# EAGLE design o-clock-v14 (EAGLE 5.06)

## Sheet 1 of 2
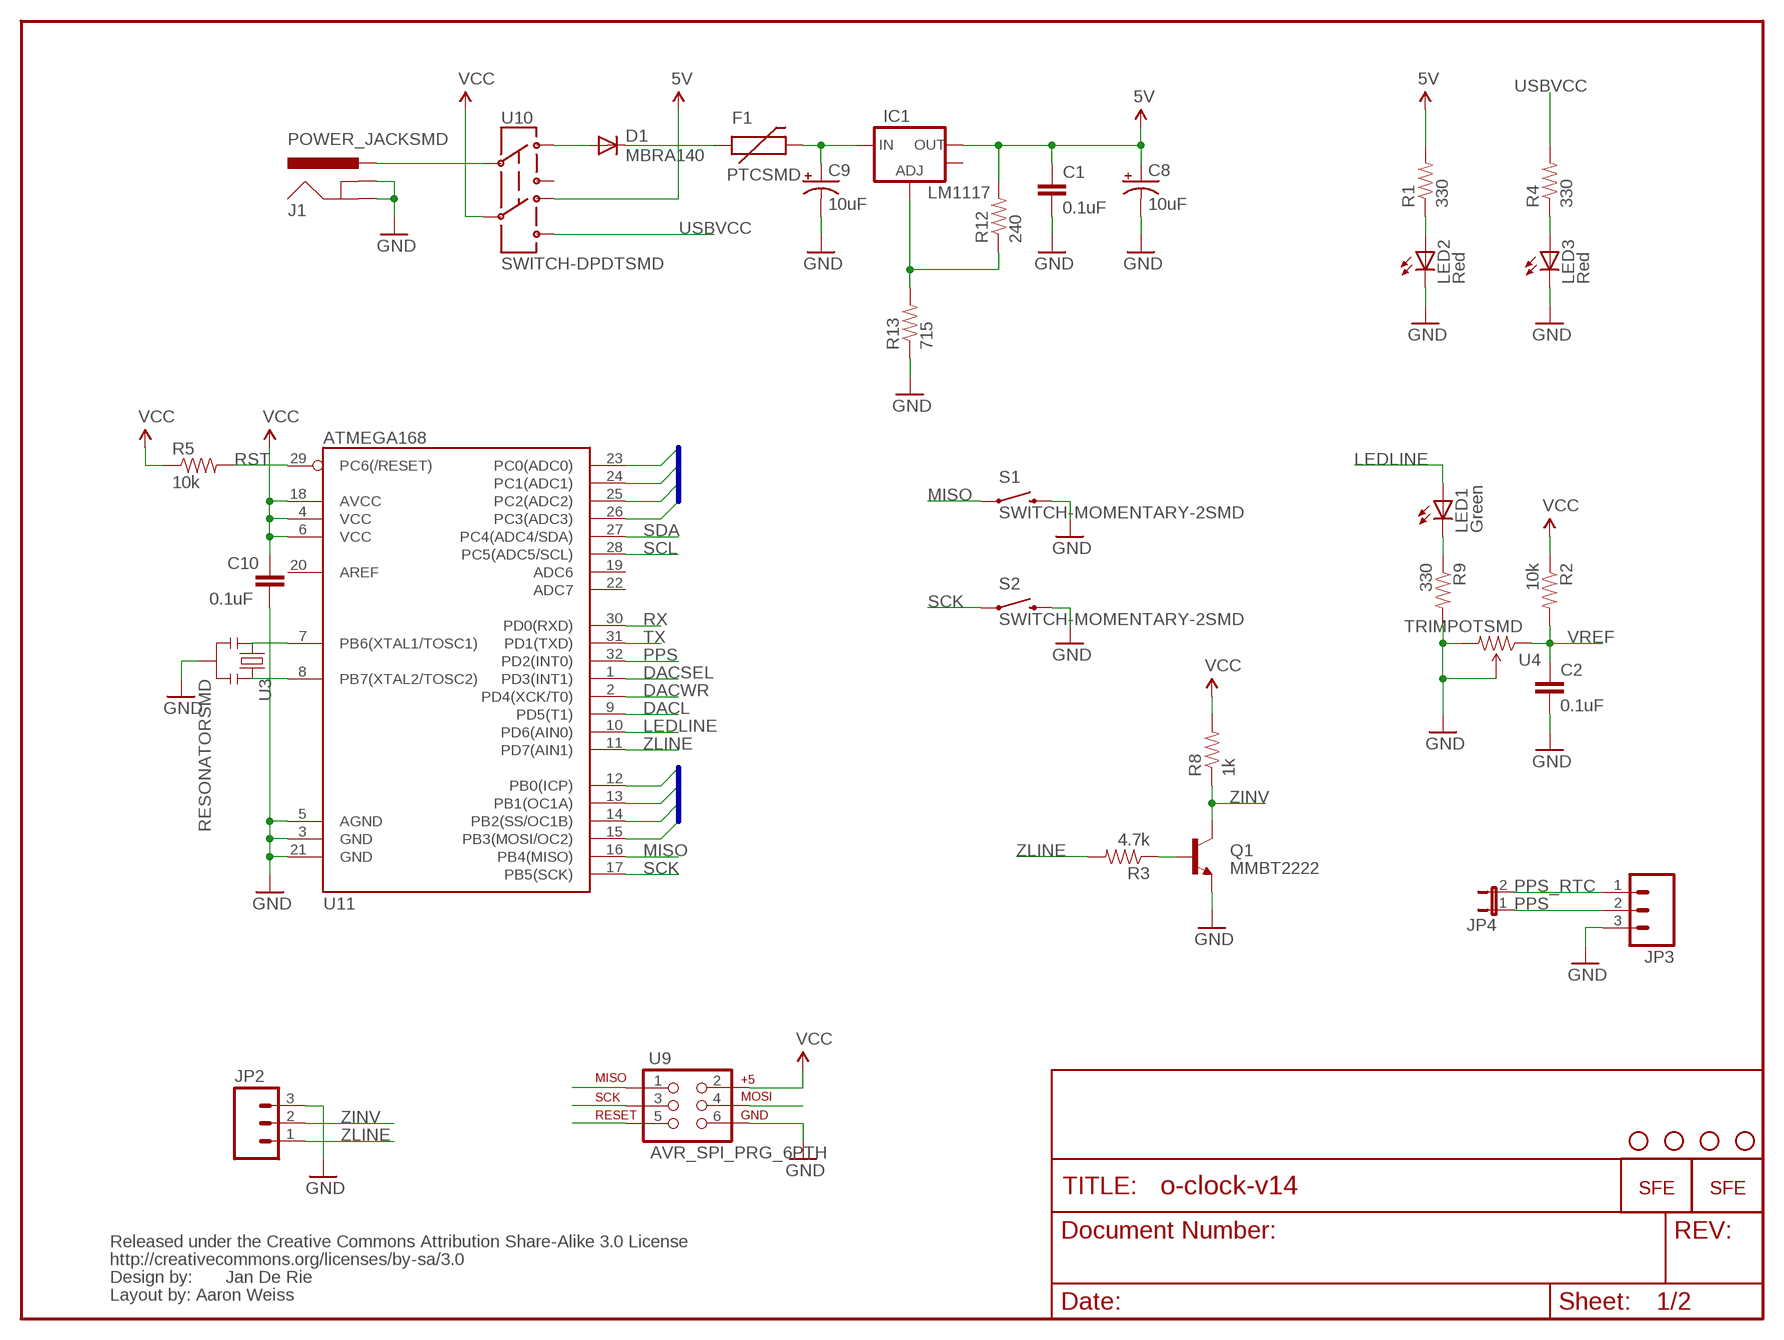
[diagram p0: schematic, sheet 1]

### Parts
C1  0.1uF  CAP0402-CAP  [0402-CAP]
C2  0.1uF  CAP0402-CAP  [0402-CAP]
C8  10uF  CAP_POL1206  [EIA3216]
C9  10uF  CAP_POL1206  [EIA3216]
C10  0.1uF  CAP0402-CAP  [0402-CAP]
D1  MBRA140  DIODESMA  [SMA-DIODE]
F1  PTCSMD  [PTC-1206]
IC1  LM1117  V_REG_LM1117SOT223  [SOT223]
J1  POWER_JACKSMD  [POWER_JACK_SMD]
JP2  M03PTH  [1X03]
JP3  M03PTH  [1X03]
JP4  JUMPER-2SMD-NC  [SJ_2S]
LED1  Green  LED0603  [LED-0603]
LED2  Red  LED0603  [LED-0603]
LED3  Red  LED0603  [LED-0603]
Q1  MMBT2222  TRANSISTOR_NPNSOT23-3  [SOT23-3]
R1  330  RESISTOR0402-RES  [0402-RES]
R2  10k  RESISTOR0402-RES  [0402-RES]
R3  4.7k  RESISTOR0402-RES  [0402-RES]
R4  330  RESISTOR0402-RES  [0402-RES]
R5  10k  RESISTOR0402-RES  [0402-RES]
R8  1k  RESISTOR0402-RES  [0402-RES]
R9  330  RESISTOR0402-RES  [0402-RES]
R12  240  RESISTOR0402-RES  [0402-RES]
R13  715  RESISTOR0402-RES  [0402-RES]
S1  SWITCH-MOMENTARY-2SMD  [TACTILE_SWITCH_SMD]
S2  SWITCH-MOMENTARY-2SMD  [TACTILE_SWITCH_SMD]
U3  RESONATORSMD  [RESONATOR-SMD]
U4  TRIMPOTSMD  [TRIMPOT-3MM]
U9  AVR_SPI_PRG_6PTH  [2X3]
U10  SWITCH-DPDTSMD  [AYZ0202]
U11  ATMEGA168  [TQFP32-08]
U$2  CREATIVE_COMMONS  [CREATIVE_COMMONS]
U$3  LOGO-SFENEW  [SFE-NEW-WEBLOGO]
U$4  STAND-OFF  [STAND-OFF]
U$5  STAND-OFF  [STAND-OFF]
U$8  STAND-OFF  [STAND-OFF]
U$9  STAND-OFF  [STAND-OFF]
U$10  LOGO-SFENEW  [SFE-NEW-WEBLOGO]

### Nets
5V: C1.1 C8.A(+) IC1.2(OUT) R1.2 R12.2 U10.4
DACL: U11.9(PD5(T1)) ; also sheet 2
DACSEL: U11.1(PD3(INT1)) ; also sheet 2
DACWR: U11.2(PD4(XCK/T0)) ; also sheet 2
GND: C1.2 C2.2 C8.C(-) C9.C(-) C10.2 J1.GND(GNDBREAK) J1.P$4(GND) JP2.3 JP3.3 LED2.C LED3.C Q1.2(E) R9.2 R13.1 S1.3 S2.3 U3.2 U4.2(WIPER) U4.3(CW) U9.6 U11.3(GND) U11.5(AGND) U11.21(GND) ; also sheet 2
LEDLINE: LED1.A U11.10(PD6(AIN0))
MISO: S1.1 U9.1 U11.16(PB4(MISO))
N$1: LED1.C R9.1
N$2: IC1.1(ADJ) R12.1 R13.2
N$3: U3.1 U11.7(PB6(XTAL1/TOSC1))
N$4: U3.3 U11.8(PB7(XTAL2/TOSC2))
N$6: J1.VIN0(PWR) U10.2
N$7: D1.A U10.1
N$8: C9.A(+) F1.2 IC1.3(IN)
N$9: LED2.A R1.1
N$10: Q1.1(B) R3.1
N$11: LED3.A R4.1
N$21: D1.C F1.1
PORTB0: U11.12(PB0(ICP)) ; also sheet 2
PORTB1: U11.13(PB1(OC1A)) ; also sheet 2
PORTB2: U11.14(PB2(SS/OC1B)) ; also sheet 2
PORTB3: U9.4 U11.15(PB3(MOSI/OC2)) ; also sheet 2
PORTC0: U11.23(PC0(ADC0)) ; also sheet 2
PORTC1: U11.24(PC1(ADC1)) ; also sheet 2
PORTC2: U11.25(PC2(ADC2)) ; also sheet 2
PORTC3: U11.26(PC3(ADC3)) ; also sheet 2
PPS: JP3.2 JP4.1 U11.32(PD2(INT0))
PPS_RTC: JP3.1 JP4.2 ; also sheet 2
RST: R5.2 U9.5 U11.29(PC6(/RESET))
RX: U11.30(PD0(RXD)) ; also sheet 2
SCK: S2.1 U9.3 U11.17(PB5(SCK))
SCL: U11.28(PC5(ADC5/SCL)) ; also sheet 2
SDA: U11.27(PC4(ADC4/SDA)) ; also sheet 2
TX: U11.31(PD1(TXD)) ; also sheet 2
USBVCC: R4.2 U10.6 ; also sheet 2
VCC: C10.1 R2.1 R5.1 R8.2 U9.2 U10.5 U11.4(VCC) U11.6(VCC) U11.18(AVCC) ; also sheet 2
VREF: C2.1 R2.2 U4.1(CCW) ; also sheet 2
ZINV: JP2.2 Q1.3(C) R8.1
ZLINE: JP2.1 R3.2 U11.11(PD7(AIN1))
Unconnected: IC1.4(OUT) U10.3 U11.19(ADC6) U11.20(AREF) U11.22(ADC7)

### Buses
PORTC[0..3]
PORTB[0..3]

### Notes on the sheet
- Jan De Rie
- Layout by: Aaron Weiss

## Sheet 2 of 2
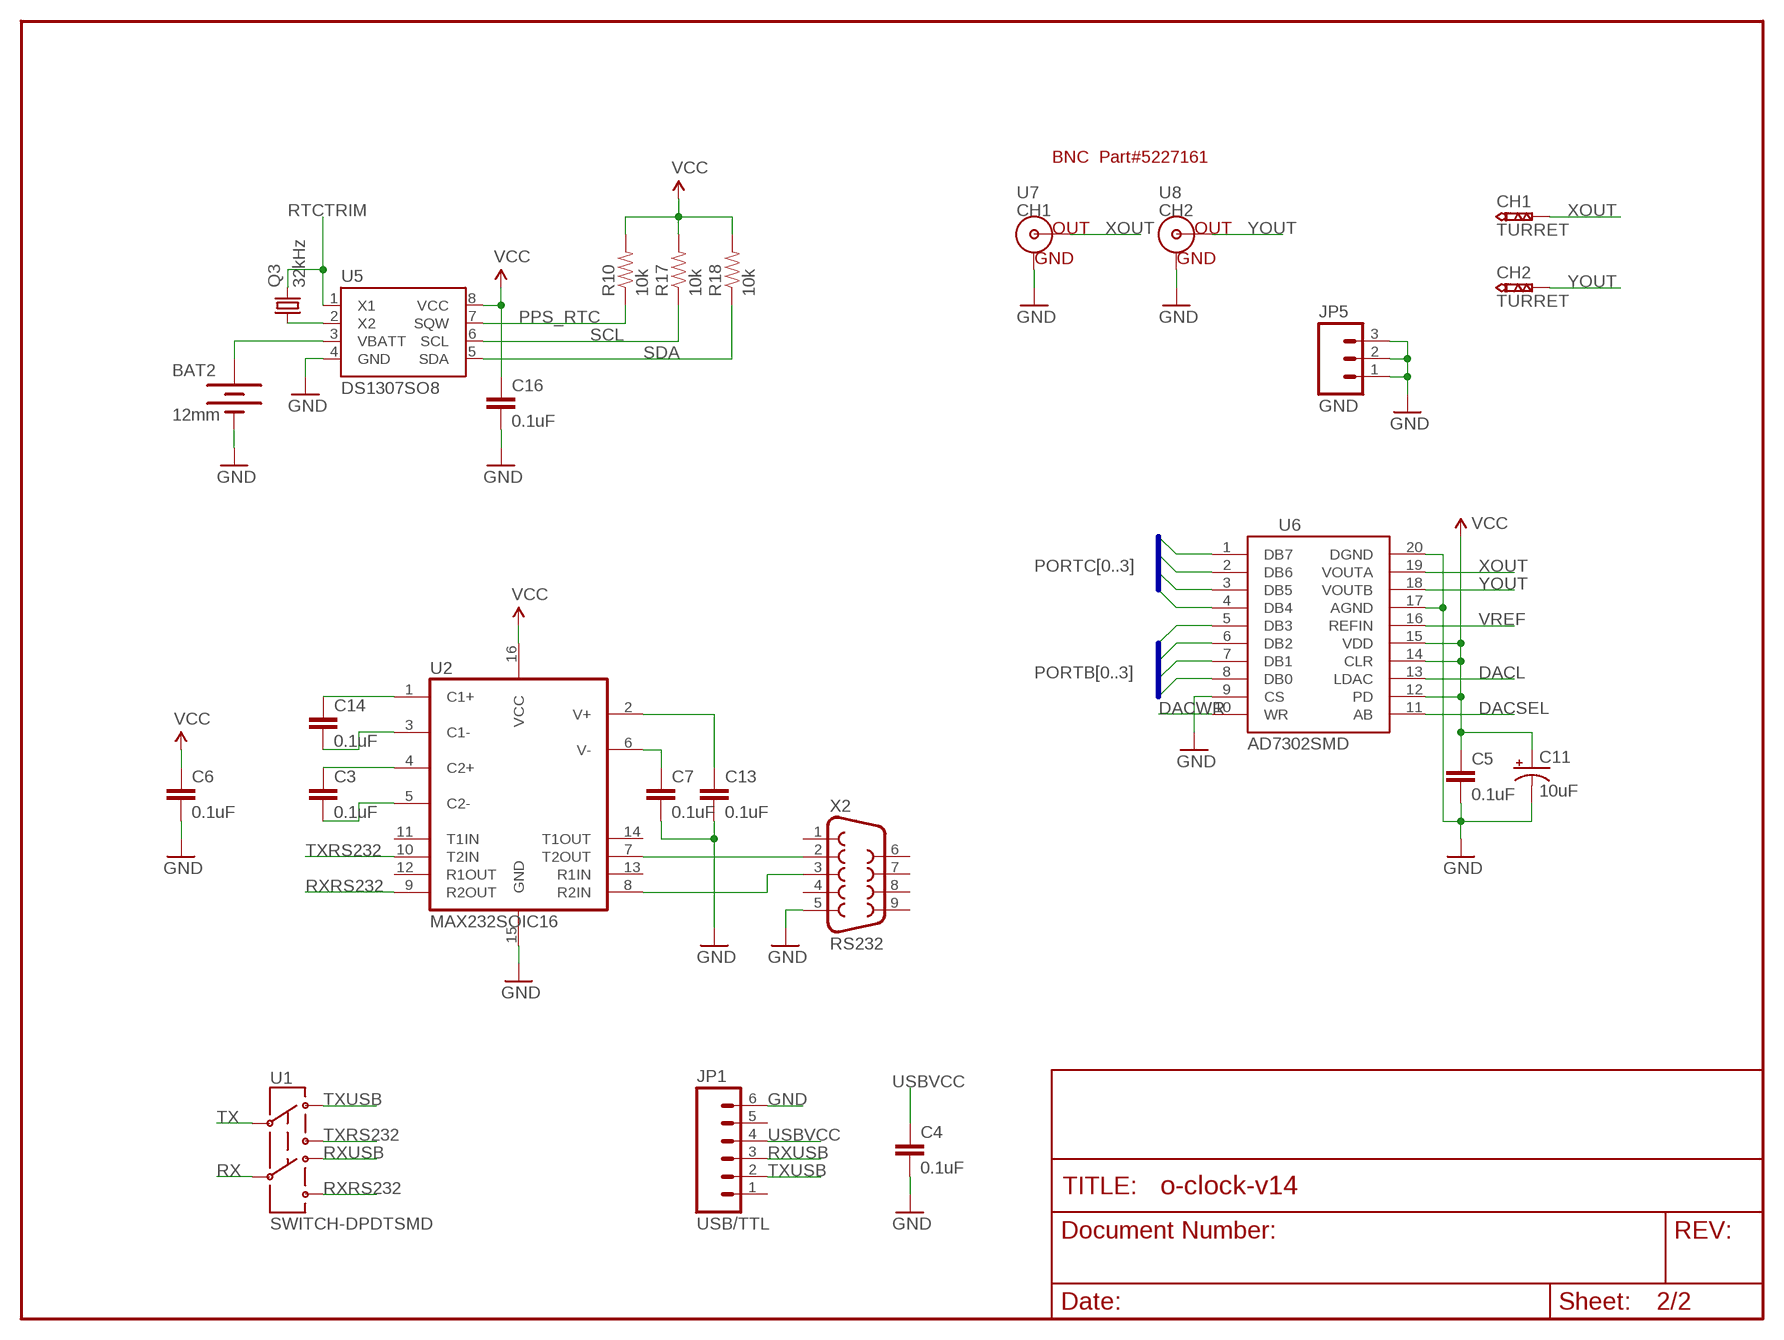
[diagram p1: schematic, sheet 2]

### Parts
BAT2  12mm  BATTERY12MM  [BATTCON_12MM]
C3  0.1uF  CAP0402-CAP  [0402-CAP]
C4  0.1uF  CAP0402-CAP  [0402-CAP]
C5  0.1uF  CAP0402-CAP  [0402-CAP]
C6  0.1uF  CAP0402-CAP  [0402-CAP]
C7  0.1uF  CAP0402-CAP  [0402-CAP]
C11  10uF  CAP_POL1206  [EIA3216]
C13  0.1uF  CAP0402-CAP  [0402-CAP]
C14  0.1uF  CAP0402-CAP  [0402-CAP]
C16  0.1uF  CAP0402-CAP  [0402-CAP]
CH1  TURRET  TURRET-1520PTH  [1X01_TURRET]
CH2  TURRET  TURRET-1520PTH  [1X01_TURRET]
JP1  USB/TTL  M06SIP  [1X06]
JP5  GND  M03LOCK  [1X03_LOCK]
Q3  32kHz  CRYSTAL32-SMD  [CRYSTAL-32KHZ-SMD]
R10  10k  RESISTOR0402-RES  [0402-RES]
R17  10k  RESISTOR0402-RES  [0402-RES]
R18  10k  RESISTOR0402-RES  [0402-RES]
U1  SWITCH-DPDTSMD  [AYZ0202]
U2  MAX232SOIC16  [SO016]
U5  DS1307SO8  [SO08]
U6  AD7302SMD  [TSSOP20]
U7  CH1  BNCPTH  [BNC]
U8  CH2  BNCPTH  [BNC]
X2  RS232  DB9  [DB9]

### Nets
DACL: U6.13(LDAC) ; also sheet 1
DACSEL: U6.11(AB) ; also sheet 1
DACWR: U6.10(WR) ; also sheet 1
GND: BAT2.GND(-) C4.2 C5.2 C6.2 C7.2 C11.C(-) C13.2 C16.2 JP1.6 JP5.1 JP5.2 JP5.3 U2.15(GND) U5.4(GND) U6.9(CS) U6.17(AGND) U6.20(DGND) U7.GND U8.GND X2.5 ; also sheet 1
N$5: BAT2.PWR@1(+) U5.3(VBATT)
N$12: C14.1 U2.1(C1+)
N$13: C14.2 U2.3(C1-)
N$14: C3.1 U2.4(C2+)
N$15: C3.2 U2.5(C2-)
N$16: C7.1 U2.6(V-)
N$17: C13.1 U2.2(V+)
N$18: U2.7(T2OUT) X2.2
N$19: U2.8(R2IN) X2.3
N$20: Q3.X1 U5.2(X2)
PORTB0: U6.8(DB0) ; also sheet 1
PORTB1: U6.7(DB1) ; also sheet 1
PORTB2: U6.6(DB2) ; also sheet 1
PORTB3: U6.5(DB3) ; also sheet 1
PORTC0: U6.4(DB4) ; also sheet 1
PORTC1: U6.3(DB5) ; also sheet 1
PORTC2: U6.2(DB6) ; also sheet 1
PORTC3: U6.1(DB7) ; also sheet 1
PPS_RTC: R10.1 U5.7(SQW) ; also sheet 1
RTCTRIM: Q3.X2 U5.1(X1)
RX: U1.5 ; also sheet 1
RXRS232: U1.6 U2.9(R2OUT)
RXUSB: JP1.3 U1.4
SCL: R17.1 U5.6(SCL) ; also sheet 1
SDA: R18.1 U5.5(SDA) ; also sheet 1
TX: U1.2 ; also sheet 1
TXRS232: U1.3 U2.10(T2IN)
TXUSB: JP1.2 U1.1
USBVCC: C4.1 JP1.4 ; also sheet 1
VCC: C5.1 C6.1 C11.A(+) C16.1 R10.2 R17.2 R18.2 U2.16(VCC) U5.8(VCC) U6.12(PD) U6.14(CLR) U6.15(VDD) ; also sheet 1
VREF: U6.16(REFIN) ; also sheet 1
XOUT: CH1.1 U6.19(VOUTA) U7.S(OUT)
YOUT: CH2.1 U6.18(VOUTB) U8.S(OUT)
Unconnected: JP1.1 JP1.5 U2.11(T1IN) U2.12(R1OUT) U2.13(R1IN) U2.14(T1OUT) X2.1 X2.4 X2.6 X2.7 X2.8 X2.9

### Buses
PORTC[0..3]
PORTB[0..3]

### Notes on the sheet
- BNC  Part#5227161

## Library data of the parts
BAT2 = SparkFun:BATTERY: Battery Holders
C1-C7 C10 C13 C14 C16 = SparkFun:CAP: Capacitor
C8 C9 C11 = SparkFun:CAP_POL: Capacitor Polarized
CH1 CH2 = SparkFun:TURRET-1520: Turret FP for Keystone Electronics Part#1520
D1 = SparkFun:DIODE: Diode
F1 = SparkFun:PTC: Resettable Fuse PTC
IC1 = SparkFun:V_REG_LM1117: Voltage Regulator LM1117 Standard adjustable voltage regulator but in SMD form. Spark Fun Electronics SKU : COM-00595
J1 = SparkFun:POWER_JACK: Power Jack This is the standard 5.5mm barrel jack for power. The PTH is the most common, proven, reliable, footprint. All others are experimental. The Slot footprint only works if the mill layer is transmitted to the PCB fab house so be warned. Spark Fun Electronics SKU : PRT-00119. Mating wall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
JP1 = SparkFun:M06: Header 6 Standard 6-pin 0.1" header. Use with straight break away headers (SKU : PRT-00116), right angle break away headers (PRT-00553), swiss pins (PRT-00743), machine pins (PRT-00117), and female headers (PRT-00115). Molex polarized connector foot print use with SKU : PRT-08094 with associated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
JP2 JP3 JP5 = SparkFun:M03: Header 3 Standard 3-pin 0.1" header. Use with straight break away headers (SKU : PRT-00116), right angle break away headers (PRT-00553), swiss pins (PRT-00743), machine pins (PRT-00117), and female headers (PRT-00115). Molex polarized connector foot print use with SKU : PRT-08232 with associated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
JP4 = SparkFun:JUMPER-2: Jumper
LED1-LED3 = SparkFun:LED: LEDs
Q1 = SparkFun:TRANSISTOR_NPN: Transistor NPN BJT configuration in SOT23 package. MMBT2222 is the common NPN we use. Double check BCE configuration again layout.
Q3 = SparkFun:CRYSTAL: Crystals
R1-R5 R8-R10 R12 R13 R17 R18 = SparkFun:RESISTOR: Resistor
S1 S2 = SparkFun:SWITCH-MOMENTARY-2
U1 U10 = SparkFun:SWITCH-DPDT: DPDT Version of the COM-00597
U2 = SparkFun:MAX232: RS232 Transceiver Very common IC. This is generically called 'MAX232', but works with the 3V equivalent MAX3232 generic ICs. Field tested and mother approved. Spark Fun Electronics SKU : COM-00316 (DIP) and COM-00589 (SMD)
U3 = SparkFun:RESONATOR: Resonator Small SMD resonator. This is the itty bitty 10/20MHz resonators with built in caps. CSTCE10M0G55 and CSTCE20M0V53. Footprint has been reviewed closely but hasn't been tested yet.
U4 = SparkFun:TRIMPOT
U5 = SparkFun:DS1307
U6 = SparkFun:AD7302: AD7302
U7 U8 = SparkFun:BNC: BNC Connector, Mouser Part# 5227161
U9 = SparkFun:AVR_SPI_PRG_6: AVR ISP 6 Pin This is the reduced ISP connector for AVR programming. Common on Arduino. This footprint will take up less PCB space and can be used with a 10-pin to 6-pin adapter such as SKU: BOB-08508
U11 = SparkFun:ATMEGA168
U$2 = SparkFun:CREATIVE_COMMONS
U$3 U$10 = SparkFun:LOGO-SFE: Spark Fun Electronics PCB Logo
U$4 U$5 U$8 U$9 = SparkFun:STAND-OFF: Stand Off
X2 = SparkFun:DB9: DB9 Connector Standard DB9 (D-Sub 9) serial connector. Can be used for CAN bus as well as RS485 and RS232. Footprint production proven. Spark Fun Electronics SKU : PRT-00429

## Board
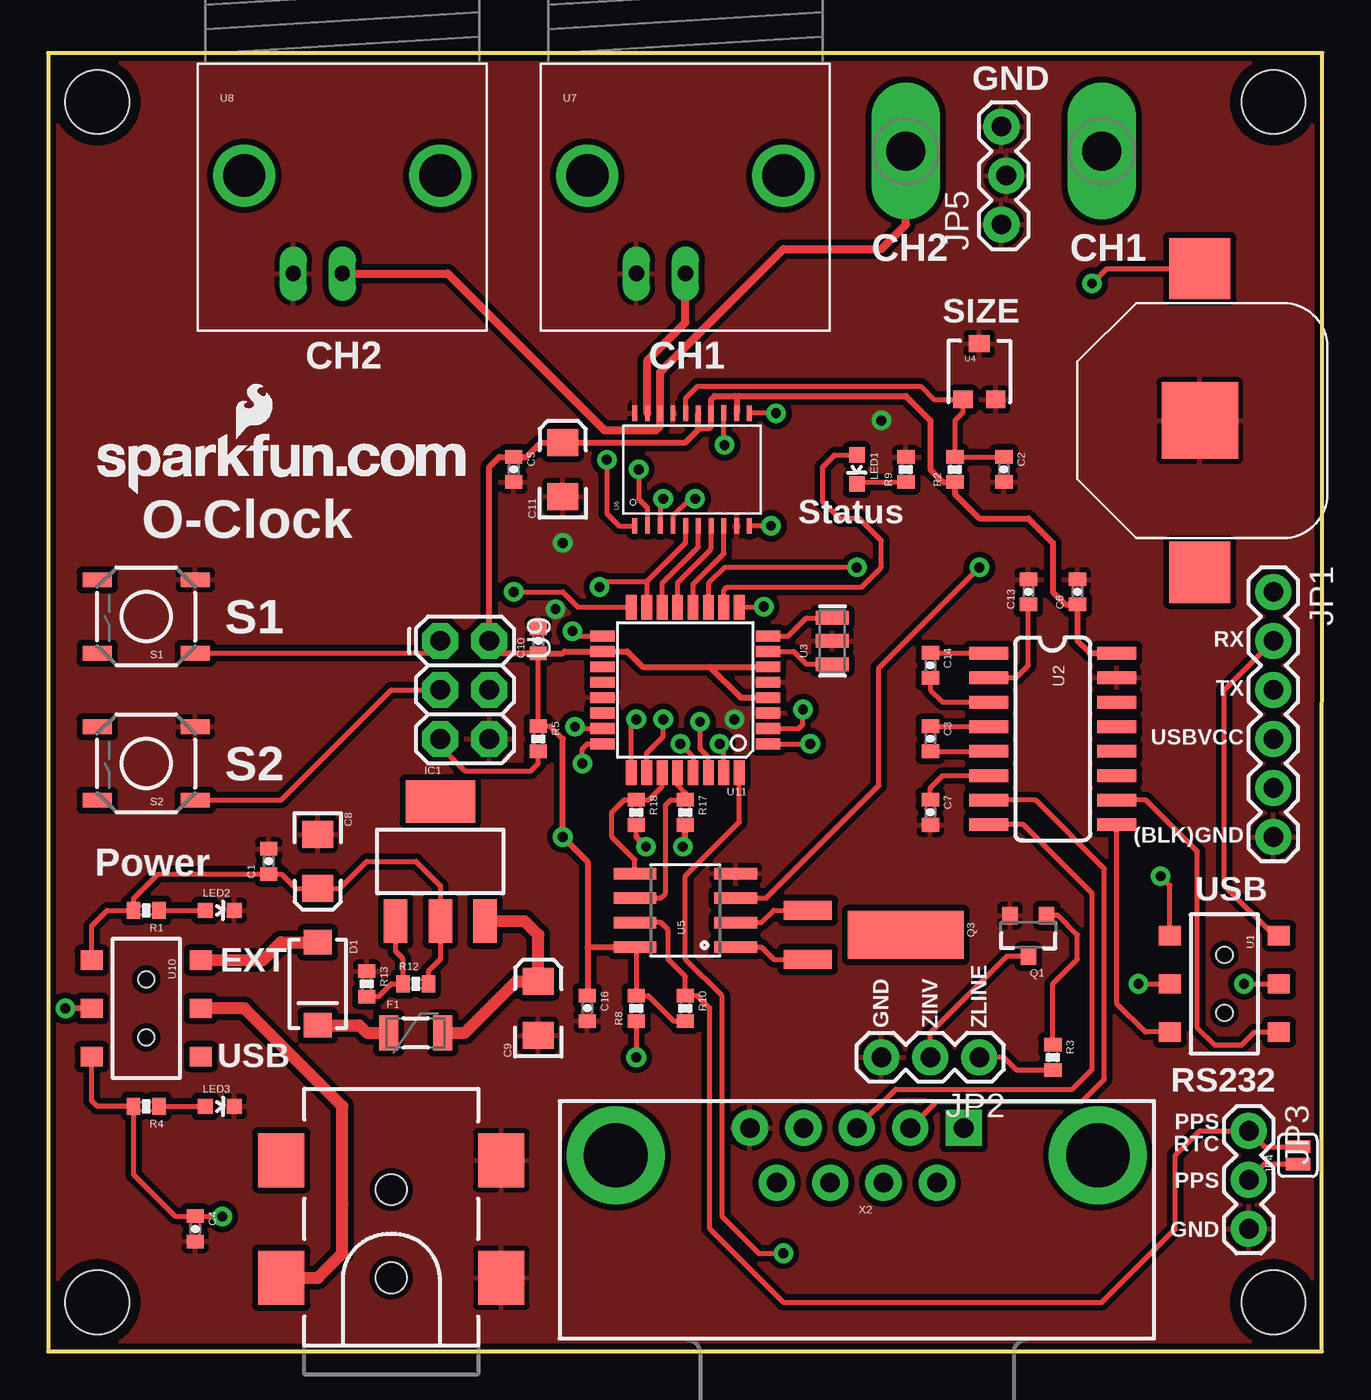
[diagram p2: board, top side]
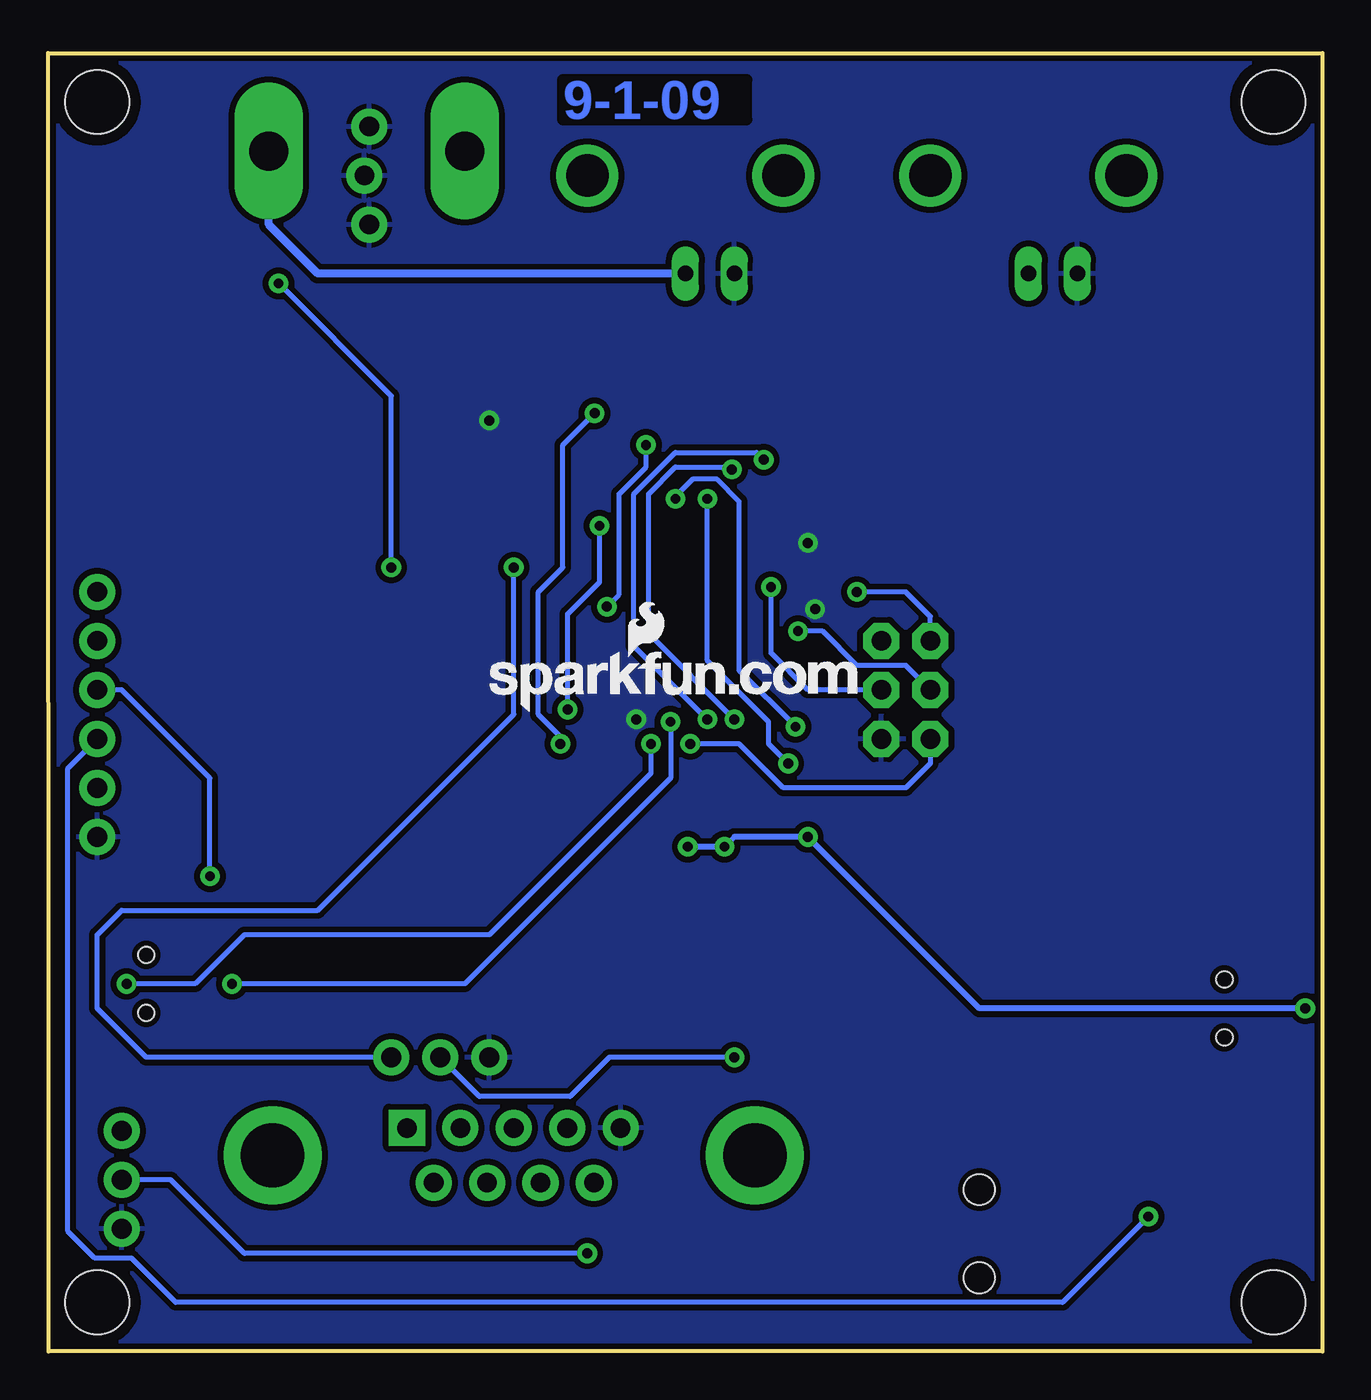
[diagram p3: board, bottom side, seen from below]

Size 66.04 x 67.31 mm. Coordinates in mm from the lower left corner, seen from the top.
Outline: 0,0 66.02,0 66.04,67.31 0,67.31 0,0
Copper layers (1*16): Top 0.035mm / dielectric 1.5mm / Bottom 0.035mm
Design rules "SparkFun": minimum track width 8mil, minimum drill 20mil, track to track 8mil, track to pad 8mil, pad to pad 8mil, via to via 8mil, smd to smd 8mil, copper to edge 9mil, drill to drill 8mil, minimum pad ring 12mil, minimum via ring 10mil, stop-mask expansion 4mil, vias tented up to drill 20mil, thermal gap 10mil

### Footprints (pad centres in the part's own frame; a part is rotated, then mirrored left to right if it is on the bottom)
BATTCON_12MM = smd 3.962 x 3.962: GND 0,0 | smd 3.175 x 3.175: PWR@1 -7.874,0; PWR@2 7.874,0
0402-CAP = smd 0.7 x 0.9: 1 -0.65,0; 2 0.65,0
EIA3216 = smd 1.4 x 1.6: A 1.4,0; C -1.4,0
1X01_TURRET = drill 2.032 pad 3.556 long: 1 0,0
SMA-DIODE = smd 1.27 x 1.47: A -2.15,0; C 2.15,0
PTC-1206 = smd 1 x 1.8: 1 -1.4,0; 2 1.4,0
SOT223 = smd 1.219 x 2.235: 1 -2.311,-3.099; 2 0,-3.099; 3 2.311,-3.099 | smd 3.6 x 2.2: 4 0,3.099
POWER_JACK_SMD = smd 2.8 x 2.4: GND 0,-5.7; P$4 6.1,-5.7; VIN0 0,5.7; VIN1 6.1,5.7 | hole 1.6: 0,0; 4.572,0
1X06 = drill 1.016 pad 1.88 round: 1 0,0; 2 2.54,0; 3 5.08,0; 4 7.62,0; 5 10.16,0; 6 12.7,0
1X03 = drill 1.016 pad 1.88 round: 1 0,0; 2 2.54,0; 3 5.08,0
SJ_2S = smd 0.635 x 1.27: 1 -0.45,0; 2 0.45,0
1X03_LOCK = drill 1.016 pad 1.88 round: 1 0,0.127; 2 2.54,-0.127; 3 5.08,0.127
LED-0603 = smd 0.8 x 0.8: A 0,-0.75; C 0,0.75
SOT23-3 = smd 0.8 x 0.9: 1 -0.95,-1; 2 0.95,-1; 3 0,1.1
CRYSTAL-32KHZ-SMD = smd 2.5 x 6: SHEILD 0,5.08 | smd 1 x 2.5: X1 -1.27,0; X2 1.27,0
0402-RES = smd 0.7 x 0.9: 1 -0.65,0; 2 0.65,0
TACTILE_SWITCH_SMD = smd 1.524 x 0.762: 1 -2.54,1.905; 2 2.54,1.905; 3 -2.54,-1.905; 4 2.54,-1.905
AYZ0202 = smd 1 x 1.15: 1 -2.5,2.825; 2 0,2.825; 3 2.5,2.825; 4 -2.5,-2.825; 5 0,-2.825; 6 2.5,-2.825 | hole 0.85: 1.5,0; -1.5,0
SO016 = smd 0.66 x 2.032: 1 -4.445,-3.315; 2 -3.175,-3.315; 3 -1.905,-3.315; 4 -0.635,-3.315; 5 0.635,-3.315; 6 1.905,-3.315; 7 3.175,-3.315; 8 4.445,-3.315; 9 4.445,3.315; 10 3.175,3.315; 11 1.905,3.315; 12 0.635,3.315; 13 -0.635,3.315; 14 -1.905,3.315; 15 -3.175,3.315; 16 -4.445,3.315
RESONATOR-SMD = smd 0.7 x 1.7: 1 -1.2,0; 2 0,0; 3 1.2,0
TRIMPOT-3MM = smd 1 x 0.9: 1 -0.85,-1.45; 3 0.85,-1.45 | smd 1.1 x 0.9: 2 0,1.45
SO08 = smd 0.61 x 2.21: 1 -1.905,-2.616; 2 -0.635,-2.616; 3 0.635,-2.616; 4 1.905,-2.616; 5 1.905,2.616; 6 0.635,2.616; 7 -0.635,2.616; 8 -1.905,2.616
TSSOP20 = smd 0.8 x 0.25: 1 -2.921,2.623; 2 -2.921,1.962; 3 -2.921,1.302; 4 -2.921,0.642; 5 -2.921,-0.019; 6 -2.921,-0.679; 7 -2.921,-1.34; 8 -2.927,-2; 9 -2.921,-2.66; 10 -2.921,-3.321; 11 2.921,-3.321; 12 2.921,-2.66; 13 2.927,-2; 14 2.921,-1.34; 15 2.921,-0.679; 16 2.921,-0.019; 17 2.921,0.642; 18 2.921,1.302; 19 2.921,1.962; 20 2.921,2.623
BNC = drill 2.2 round: 3 -5.08,5.08; 4 5.08,5.08 | drill 0.8 long: GND -2.54,0; S 0,0
2X3 = drill 1.016 pad 1.88 octagon: 1 0,0; 2 0,2.54; 3 2.54,0; 4 2.54,2.54; 5 5.08,0; 6 5.08,2.54
TQFP32-08 = smd 1.27 x 0.559: 1 -4.293,2.8; 2 -4.293,2; 3 -4.293,1.2; 4 -4.293,0.4; 5 -4.293,-0.4; 6 -4.293,-1.2; 7 -4.293,-2; 8 -4.293,-2.8; 17 4.293,-2.8; 18 4.293,-2; 19 4.293,-1.2; 20 4.293,-0.4; 21 4.293,0.4; 22 4.293,1.2; 23 4.293,2; 24 4.293,2.8 | smd 0.559 x 1.27: 9 -2.8,-4.293; 10 -2,-4.293; 11 -1.2,-4.293; 12 -0.4,-4.293; 13 0.4,-4.293; 14 1.2,-4.293; 15 2,-4.293; 16 2.8,-4.293; 25 2.8,4.293; 26 2,4.293; 27 1.2,4.293; 28 0.4,4.293; 29 -0.4,4.293; 30 -1.2,4.293; 31 -2,4.293; 32 -2.8,4.293
STAND-OFF = hole 3.302: 0,0
DB9 = drill 1.016 pad 1.88 square: 1 -5.54,-1.42 | drill 1.016 pad 1.88 round: 2 -2.77,-1.42; 3 0,-1.42; 4 2.77,-1.42; 5 5.54,-1.42; 6 -4.15,1.42; 7 -1.38,1.42; 8 1.38,1.42; 9 4.15,1.42 | drill 3.302 pad 5.08 round: G1 -12.5,0; G2 12.5,0

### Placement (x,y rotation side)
BAT2  59.69,48.26 270 top
C1  11.43,25.4 90 top
C2  49.53,45.72 270 top
C3  45.72,31.75 270 top
C4  7.62,6.35 270 top
C5  24.13,45.72 270 top
C6  53.34,39.37 90 top
C7  45.72,27.94 270 top
C8  13.97,25.4 270 top
C9  25.4,17.78 90 top
C10  25.4,36.83 90 top
C11  26.67,45.72 90 top
C13  50.8,39.37 90 top
C14  45.72,35.56 270 top
C16  27.94,17.78 270 top
CH1  54.61,62.23 0 top
CH2  44.45,62.23 0 top
D1  13.97,19.05 270 top
F1  19.05,16.51 0 top
IC1  20.32,25.4 0 top
J1  17.78,3.81 90 top
JP1  63.5,39.37 270 top
JP2  48.26,15.24 180 top
JP3  62.23,11.43 270 top
JP4  64.77,10.16 90 top
JP5  49.53,58.42 90 top
LED1  41.91,45.72 180 top
LED2  8.89,22.86 270 top
LED3  8.89,12.7 270 top
Q1  50.8,21.59 180 top
Q3  39.37,21.59 270 top
R1  5.08,22.86 180 top
R2  46.99,45.72 90 top
R3  52.07,15.24 270 top
R4  5.08,12.7 180 top
R5  25.4,31.75 270 top
R8  30.48,17.78 90 top
R9  44.45,45.72 90 top
R10  33.02,17.78 270 top
R12  19.05,19.05 0 top
R13  16.51,19.05 270 top
R17  33.02,27.94 270 top
R18  30.48,27.94 270 top
S1  5.08,38.1 180 top
S2  5.08,30.48 180 top
U1  60.96,19.05 270 top
U2  52.07,31.75 270 top
U3  40.64,36.83 90 top
U4  48.26,50.8 0 top
U5  33.02,22.86 90 top
U6  33.02,45.72 90 top
U7  33.02,55.88 0 top
U8  15.24,55.88 0 top
U9  20.32,36.83 270 top
U10  5.08,17.78 270 top
U11  33.02,34.29 180 top
U$2  not placed on the board
U$3  43.18,33.15 0 bottom
U$4  2.54,2.54 0 top
U$5  63.5,2.54 0 top
U$8  2.54,64.77 0 top
U$9  63.5,64.77 0 top
U$10  2.54,44.45 0 top
X2  41.91,10.16 180 top

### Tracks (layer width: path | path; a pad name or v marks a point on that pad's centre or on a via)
5V
  Top 0.254: R12.2 19.7,19.7 20.32,20.32 IC1.2 20.32,24.13 19.05,25.4 16.51,25.4 15.11,24 C8.A 12.83,24 12.08,24.75 C1.1 5.7,24.75 4.43,23.48 R1.2 3.05,22.86 2.25,22.07 U10.4
DACL  (via drill 0.51)
  Top 0.254: U11.9 37.06,38.58 v37.08,38.61 | U6.13 35.02,47.02 v35.05,46.99
  Bottom 0.254: v35.05,46.99 35.05,45.85 36.45,44.45 36.45,39.24 v37.08,38.61
DACSEL  (via drill 0.51)
  Top 0.254: v37.72,48.64 U6.11 | U11.1 v39.49,31.49 v39.5,31.5
  Bottom 0.254: v39.5,31.5 39.5,31.88 40.64,33.02 40.64,39.37 39.37,40.64 39.37,46.99 v37.72,48.64
DACWR  (via drill 0.51)
  Top 0.254: U11.2 38.89,32.29 39.12,32.51 v39.12,33.27 | v37.47,42.8 U6.10
  Bottom 0.254: v37.47,42.8 37.47,39.88 39.12,38.23 v39.12,33.27
GND  (via drill 0.51)
  other vias: 26.29,38.48 26.67,41.91 43.18,48.26 35.56,32.77
  pour Bottom (isolate 0.305): 0,67.31 0,0 66.04,0 66.04,67.31
  pour Top (isolate 0.305): 0,67.31 66.04,67.31 66.04,0 0,0
LEDLINE
  Top 0.254: U11.10 35.02,39.47 35.18,39.62 42.16,39.62 43.18,40.64 43.18,42.04 42.04,43.18 41.02,43.18 40.13,44.07 40.13,45.85 40.76,46.47 LED1.A
MISO  (via drill 0.51)
  Top 0.254: U11.16 27.46,38.58 26.67,39.37 v24.13,39.37 | S1.1 19.68,36.2 U9.1
  Bottom 0.254: U9.1 20.32,38.1 21.59,39.37 v24.13,39.37
N$1
  Top 0.254: R9.1 42.01,45.07 LED1.C
N$2
  Top 0.254: R13.2 17.13,18.4 17.78,19.05 R12.1 18.4,20.34 18.01,20.73 IC1.1
N$3
  Top 0.254: U11.7 38.64,36.29 39.3,35.63 U3.1
N$4
  Top 0.254: U11.8 38.36,37.09 39.3,38.03 U3.3
N$5  (via drill 0.51)
  Top 0.254: U5.3 37.21,23.5 43.05,29.34 43.05,35.43 v48.26,40.64 | BAT2.PWR@1 54.86,56.13 v54.1,55.37
  Bottom 0.254: v48.26,40.64 48.26,49.53 v54.1,55.37
N$6
  Top 0.61: U10.2 10.16,17.78 15.24,12.7 15.24,7.62 15.24,5.08 13.97,3.81 J1.VIN0
N$7
  Top 0.61: U10.1 11.14,20.28 12.06,21.2 D1.A
N$8
  Top 0.61: F1.2 21.59,16.51 24.26,19.18 C9.A 25.4,21.59 24.69,22.3 IC1.3
N$9
  Top 0.254: R1.1 LED2.A
N$10
  Top 0.254: Q1.1 52.34,22.59 53.34,21.59 53.34,20.32 52.07,19.05 R3.1
N$11
  Top 0.254: R4.1 LED3.A
N$12
  Top 0.254: U2.1 45.73,36.2 C14.1
N$13
  Top 0.254: C14.2 45.72,34.29 46.35,33.66 U2.3
N$14
  Top 0.254: U2.4 45.73,32.38 C3.1
N$15
  Top 0.254: C3.2 48.74,31.1 U2.5
N$16
  Top 0.254: U2.6 46.35,29.84 45.72,29.21 C7.1
N$17
  Top 0.254: U2.2 50.16,34.92 50.8,35.56 C13.1
N$18
  Top 0.254: U2.7 51.18,28.57 54.74,25.02 54.74,14.1 53.59,12.95 46.05,12.95 X2.2
N$19
  Top 0.254: U2.8 50.55,27.3 54.1,23.75 54.1,14.61 53.09,13.59 43.92,13.59 X2.3
N$20
  Top 0.254: Q3.X1 37.59,22.86 36.96,22.23 U5.2
N$21
  Top 0.61: D1.C 16.12,16.9 16.51,16.51 F1.1
PORTB0
  Top 0.254: U6.8 35.02,41.37 33.42,39.77 U11.12
PORTB1
  Top 0.254: U11.13 32.62,39.86 34.36,41.6 U6.7
PORTB2
  Top 0.254: U11.14 31.82,39.82 33.7,41.7 U6.6
PORTB3  (via drill 0.51)
  Top 0.254: 31.02,39.91 U11.15 | U6.5 33.04,41.93 31.02,39.91 | 31.02,39.91 28.86,39.91 v28.57,39.62
  Bottom 0.254: v28.57,39.62 28.57,36.2 26.67,34.29 U9.4
PORTC0  (via drill 0.51)
  Top 0.254: U11.23 27.4,32.29 v27.3,32.38 | U6.4 32.38,43.3 33.27,44.2 v33.53,44.2
  Bottom 0.254: v33.53,44.2 33.53,44.32 32.64,45.21 31.37,45.21 30.23,44.07 30.23,35.31 v27.3,32.38
PORTC1  (via drill 0.51)
  Top 0.254: U11.24 27.93,31.49 27.69,31.24 v27.69,30.48 | U6.3 31.72,44.04 v31.88,44.2
  Bottom 0.254: v31.88,44.2 31.88,35.81 28.7,32.64 28.7,31.5 v27.69,30.48
PORTC2  (via drill 0.51)
  Top 0.254: U11.25 30.22,32.51 v30.48,32.77 | U6.2 31.06,43.74 30.61,44.2 v30.61,45.72
  Bottom 0.254: v30.48,32.77 34.92,37.21 34.92,44.45 33.53,45.85 30.73,45.85 v30.61,45.72
PORTC3  (via drill 0.51)
  Top 0.254: U11.26 31.02,31.02 31.88,31.88 v31.88,32.77 | U6.1 29.59,42.8 28.96,43.43 v28.96,46.23
  Bottom 0.254: v31.88,32.77 35.69,36.58 35.69,44.45 33.53,46.61 29.34,46.61 v28.96,46.23
PPS  (via drill 0.51)
  Top 0.254: U11.32 35.82,27.44 33.02,24.64 33.02,20.32 34.92,18.41 34.92,6.99 36.83,5.08 v38.1,5.08 | JP4.1 63.05,9.71 JP3.2
  Bottom 0.254: v38.1,5.08 55.88,5.08 59.69,8.89 JP3.2
PPS_RTC
  Top 0.254: U5.7 31.75,22.23 32.13,21.84 32.13,20.32 33.02,19.43 R10.1 33.64,18.43 34.29,17.78 34.29,6.35 38.1,2.54 54.61,2.54 58.42,6.35 58.42,10.16 59.69,11.43 JP3.1 63.05,10.61 JP4.2
RST  (via drill 0.51)
  Top 0.254: R5.2 25.4,30.48 25.02,30.1 21.59,30.1 20.32,31.37 U9.5 | v32.77,31.5 33.42,30.84 U11.29
  Bottom 0.254: v32.77,31.5 30.23,31.5 27.94,29.21 21.59,29.21 20.32,30.48 U9.5
RTCTRIM
  Top 0.254: Q3.X2 37.59,20.32 36.96,20.95 U5.1
RX  (via drill 0.51)
  Top 0.254: U11.30 34.22,30.8 33.78,31.24 v33.78,32.64 | v56.52,19.05 U1.5
  Bottom 0.254: v56.52,19.05 44.45,19.05 33.78,29.72 v33.78,32.64
RXRS232
  Top 0.254: U1.6 56.86,16.55 55.38,18.02 U2.9
RXUSB  (via drill 0.51)
  Top 0.254: U1.4 58.13,24.16 v57.66,24.64
  Bottom 0.254: JP1.3 62.23,34.29 57.66,29.72 v57.66,24.64
SCK  (via drill 0.51)
  Top 0.254: U9.3 17.78,34.29 12.06,28.57 S2.1 | U11.17 27.43,37.09 v27.18,37.34
  Bottom 0.254: v27.18,37.34 25.91,37.34 24.13,35.56 21.59,35.56 U9.3
SCL
  Top 0.254: U11.28 32.62,29.36 33.02,28.96 R17.1 32.27,28.59 32,28.32 32,23.75 31.75,23.5 U5.6
SDA
  Top 0.254: U5.5 30.4,25.48 29.21,26.67 29.21,27.94 29.86,28.59 R18.1 31.13,28.59 31.82,29.28 U11.27
TX  (via drill 0.51)
  Top 0.254: U11.31 35.02,31.27 v34.8,31.5 | v61.98,19.05 U1.2
  Bottom 0.254: v61.98,19.05 58.42,19.05 55.88,21.59 43.18,21.59 34.8,29.97 v34.8,31.5
TXRS232
  Top 0.254: U1.3 62.52,16.55 61.85,15.88 60.45,15.88 59.56,16.76 59.56,25.91 56.9,28.57 U2.10
TXUSB
  Top 0.254: U1.1 63.54,21.55 60.96,24.13 60.96,34.29 JP1.2
USBVCC  (via drill 0.51)
  Top 0.254: v9.02,6.99 9,7 C4.1 6.59,7 4.43,9.16 R4.2 2.54,12.7 2.25,12.98 U10.6
  Bottom 0.254: JP1.4 65.02,30.23 65.02,6.22 63.63,4.83 61.72,4.83 59.44,2.54 13.46,2.54 v9.02,6.99
VCC  (via drill 0.51)
  Top 0.254: 26.67,31.75 26.02,32.4 R5.1 C10.1 | 30.48,26.67 R18.2 | 34.29,47.88 34.36,47.95 | 33.7,47.8 33.78,47.88 | 27.95,18.45 C16.1 | U5.8 30.48,20.88 R8.2 31.1,18.43 32.4,17.13 R10.2
  Top 0.305: 26.67,31.75 v26.67,26.67 27.95,25.39 27.95,20.95 | v30.99,26.16 30.48,26.67 | R17.2 33.02,26.29 v32.89,26.16 | 27.95,20.95 U5.8 | U2.16 53.98,36.2 53.34,36.83 C6.1 52.72,38.72 52.07,39.37 52.07,41.91 50.8,43.18 48.26,43.18 46.99,44.45 R2.1 46.37,45.07 45.72,45.72 45.72,48.26 44.45,49.53 35.8,49.53 35.68,49.41 | U6.15 33.7,47.8 33.02,47.12 C11.A 25.53,47.12 24.78,46.37 C5.1 23.38,46.37 22.86,45.85 U9.2 23.51,36.18 C10.1 26.66,36.18 26.77,36.29 U11.18 30,36.29 30.8,35.49 34.29,35.49 | 34.36,47.95 U6.14 34.36,49.35 34.54,49.53 35.56,49.53 35.68,49.41 | 33.78,47.88 34.29,47.88 | 35.68,49.41 U6.12 | 34.29,35.49 U11.6 | U11.4 35.89,33.89 34.29,35.49 | U10.5 v0.89,17.78 | 27.95,20.95 27.95,18.45
  Bottom 0.254: 30.48,26.67 v30.99,26.16
  Bottom 0.305: v0.89,17.78 17.78,17.78 v26.67,26.67 30.48,26.67 | v30.99,26.16 v32.89,26.16
VREF
  Top 0.254: C2.1 R2.2 46.99,48.26 47.41,48.68 U4.1 45.9,49.35 45.21,50.04 33.66,50.04 33.04,49.42 U6.16
XOUT
  Top 0.406: U6.19 31.06,51.38 33.02,53.34 U7.S
  Bottom 0.406: U7.S 52.07,55.88 54.61,58.42 CH1.1
YOUT
  Top 0.406: U8.S 20.7,55.88 28.83,47.75 31.5,47.75 31.72,47.97 U6.18 31.72,50.77 38.1,57.15 43.18,57.15 44.45,58.42 CH2.1
ZINV  (via drill 0.51)
  Top 0.254: Q1.3 49.7,20.49 45.72,16.51 JP2.2 | R8.1 v30.48,15.24
  Bottom 0.254: v30.48,15.24 36.96,15.24 38.99,13.21 43.69,13.21 JP2.2
ZLINE  (via drill 0.51)
  Top 0.254: R3.2 50.18,14.59 49.53,15.24 JP2.1 | U11.11 34.22,39.81 35.05,40.64 v41.91,40.64
  Bottom 0.254: v41.91,40.64 41.91,33.02 52.07,22.86 62.23,22.86 63.5,21.59 63.5,17.78 60.96,15.24 JP2.1

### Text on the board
Bottom: 9-1-09
tPlace: GND | CH2 | CH1 | SIZE | CH2 | CH1 | Status | O-Clock | S1 | RX | TX | USBVCC | S2 | (BLK)GND | Power | USB | EXT | GND | ZINV | ZLINE | USB | RS232 | PPS | RTC | PPS | GND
